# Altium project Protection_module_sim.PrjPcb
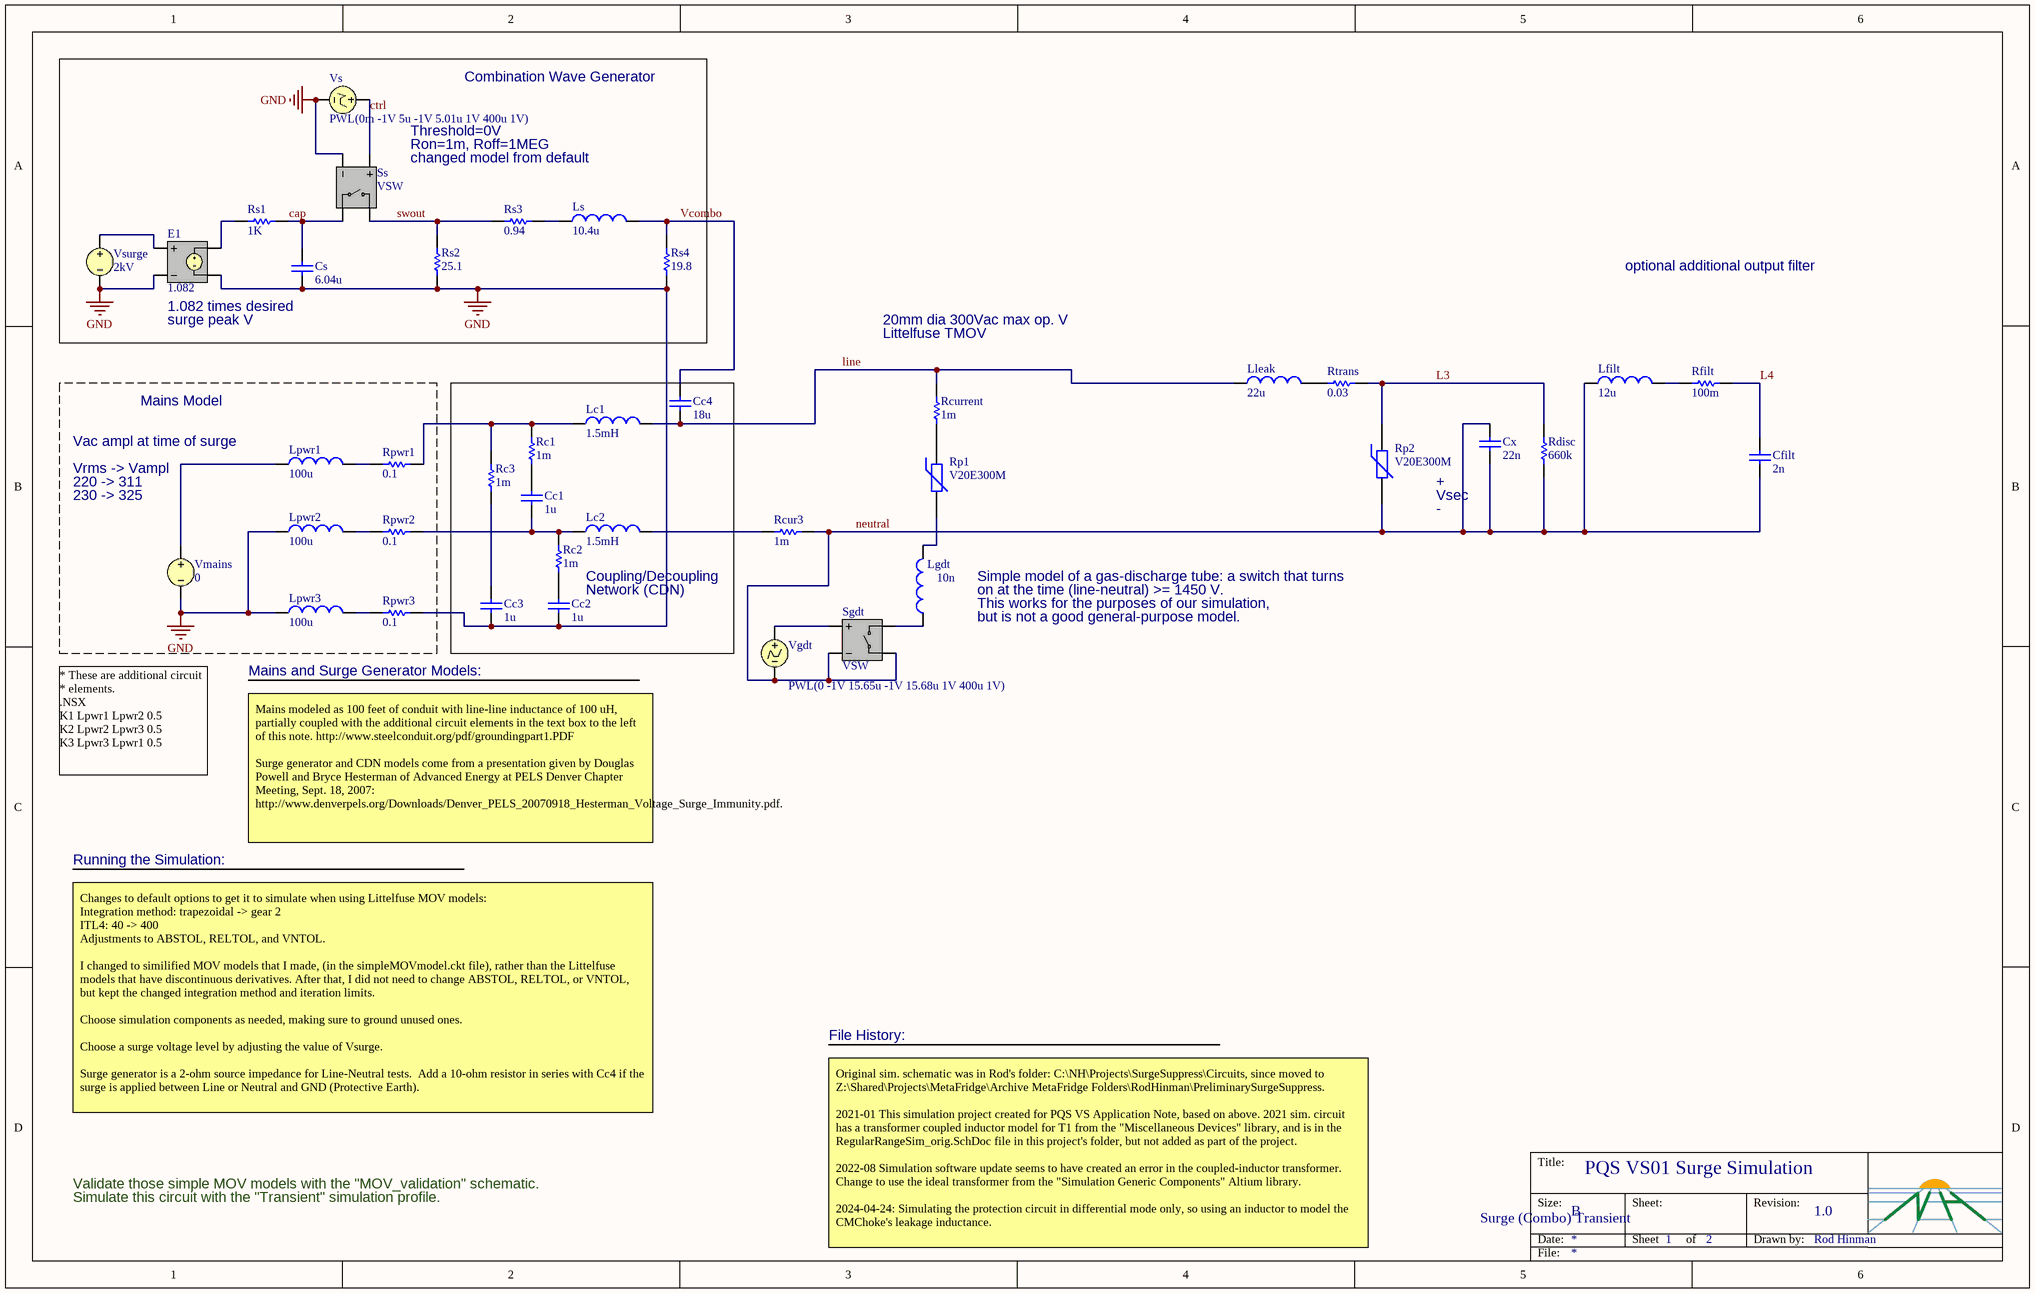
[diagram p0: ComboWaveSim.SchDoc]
nhEngName: Rod Hinman; nhProjName: PQS VS01 Surge Simulation; nhRev: 1.0; nhSheetTotal: 2
2 sheets, 52 parts. Net scope: global (net labels, ports and power ports of the same name join across sheets).
Sheets:
  ComboWaveSim.SchDoc
  MOV_validation.SchDoc

## Sheet ComboWaveSim.SchDoc: Simulation of Surge Test Combination Wave
size B; SheetNumber: 1; PageSetup: Record=PageOptions¦CenterHorizontal=True¦CenterVertical=True¦PrintScale=0.72¦XCorrection=1.00¦YCorrection=1.00¦PrintKind=0¦BorderSize=5000000¦LeftOffset=0¦BottomOffset=0¦Orientation=2¦PaperLength=1000¦PaperWidth=1000¦Scale=100¦PaperSource=7¦PrintQuality=-4¦MediaType=1¦DitherType=10¦PrintScaleMode=1¦PaperKind=Letter¦PaperIndex=1; nhSheetName: Surge (Combo) Transient; SPICEModelCacheWJGPQAWH: <root> / <DocumentId>WJGPQAWH</DocumentId> / <CacheFrame Number="0"> / <Model Name="vlowr" Kind="mdl"> / <Text>.MODEL VLOWR VSWITCH(RON=1m ROFF=1MEG)</Text> / </Model> / <Model Name="v20e300m" Kind="CKT"> / <Text>* Littelfuse UMOV V20E300: 20 mm disc 300VAC working voltage / * This curve was fit starting with two points from the max. clamping curve: / * Current Datasheet  Simulation with Io=0.6e-3 / *    10A  675V       612V / *   100A  775V       760V / *  1000A  920V       904V / * Then simulating and seeing the results. / * Using the first two points (which is where we'd like to operate in a dual-MOV system) / * Vo = 43.4V, Io = 4.8e-6A / * Using the second two points (100A, 1000A), we get: / * Vo = 63V, Io = 1.2e-3A / * These are on the _max_ curve, while it looks like Littelfuse simulates more typical values. / .subckt V20E300M 1 2 / R1 1 3 100u / B1 3 4 I=0.6e-3*(exp(abs(V(3,4))/63)-1)*sgn(V(3,4)) / C1 3 4 800pF / R2 3 4 4g / L1 4 2 12nH / .ends</Text> / </Model> / </CacheFrame> / </root>

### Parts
Cc1  1u  [RAD-0.3]
Cc2  1u  [RAD-0.3]
Cc3  1u  [RAD-0.3]
Cc4  18u  [RAD-0.3]
Cfilt  2n  [RAD-0.3]
Cs  6.04u  [RAD-0.3]
Cx  22n  [RAD-0.3]
E1  1.082
Lc1  1.5mH  [0402-A]
Lc2  1.5mH  [0402-A]
Lfilt  12u  [0402-A]
Lgdt  10n  [0402-A]
Lleak  22u  [0402-A]
Lpwr1  100u  [0402-A]
Lpwr2  100u  [0402-A]
Lpwr3  100u  [0402-A]
Ls  10.4u  [0402-A]
Rc1  1m  [AXIAL-0.3]
Rc2  1m  [AXIAL-0.3]
Rc3  1m  [AXIAL-0.3]
Rcur3  1m  [AXIAL-0.3]
Rcurrent  1m  [AXIAL-0.3]
Rdisc  660k  [AXIAL-0.3]
Rfilt  100m  [AXIAL-0.3]
Rp1  V20E300M  [6-0805_L]
Rp2  V20E300M  [6-0805_L]
Rpwr1  0.1  [AXIAL-0.3]
Rpwr2  0.1  [AXIAL-0.3]
Rpwr3  0.1  [AXIAL-0.3]
Rs1  1K  [AXIAL-0.3]
Rs2  25.1  [AXIAL-0.3]
Rs3  0.94  [AXIAL-0.3]
Rs4  19.8  [AXIAL-0.3]
Rtrans  0.03  [AXIAL-0.3]
Sgdt  VSW
Ss  VSW
Vgdt  PWL(0 -1V 15.65u -1V 15.68u 1V 400u 1V)
Vmains  0
Vs  PWL(0m -1V 5u -1V 5.01u 1V 400u 1V)
Vsurge  2kV

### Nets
GND: Cc2.2 Cc3.2 Cs.2 E1.2(NC-) E1.4(N-) Lpwr2.1 Lpwr3.1 Rpwr3.2 Rs2.1 Rs4.1 Ss.2(N1-) Vmains.2 Vs.2 Vsurge.2
cap: Cs.1 Rs1.2 Ss.4(N2-)
ctrl: Ss.1(N1+) Vs.1
L3: Rdisc.2 Rp2.1 Rtrans.2
L4: Cfilt.1 Rfilt.1
line: Cc4.2 Lc1.2 Lleak.1 Rcurrent.1
neutral: Cfilt.2 Cx.1 Cx.2 Lfilt.1 Rcur3.1 Rdisc.1 Rp2.2 Sgdt.2(N1-) Sgdt.4(N2-) Vgdt.2
swout: Rs2.2 Rs3.2 Ss.3(N2+)
Vcombo: Cc4.1 Ls.2 Rs4.2
NetCc1_1: Cc1.1 Rc1.2
NetCc1_2: Cc1.2 Lc2.1 Rc2.1 Rpwr2.2
NetCc2_1: Cc2.1 Rc2.2
NetCc3_1: Cc3.1 Rc3.2
NetE1_1: E1.1(NC+) Vsurge.1
NetE1_3: E1.3(N+) Rs1.1
NetLc1_1: Lc1.1 Rc1.1 Rc3.1 Rpwr1.2
NetLc2_2: Lc2.2 Rcur3.2
NetLfilt_2: Lfilt.2 Rfilt.2
NetLgdt_1: Lgdt.1 Sgdt.3(N2+)
NetLgdt_2: Lgdt.2 Rp1.2
NetLleak_2: Lleak.2 Rtrans.1
NetLpwr1_1: Lpwr1.1 Vmains.1
NetLpwr1_2: Lpwr1.2 Rpwr1.1
NetLpwr2_2: Lpwr2.2 Rpwr2.1
NetLpwr3_2: Lpwr3.2 Rpwr3.1
NetLs_1: Ls.1 Rs3.1
NetRcurrent_2: Rcurrent.2 Rp1.1
NetSgdt_1: Sgdt.1(N1+) Vgdt.1

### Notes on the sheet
- Combination Wave Generator
- changed model from default
- Ron=1m, Roff=1MEG
- Threshold=0V
- optional additional output filter
- 1.082 times desired
- surge peak V
- 20mm dia 300Vac max op. V
- Littelfuse TMOV
- Mains Model
- Vrms -> Vampl
- 220 -> 311
- (near Lpwr1) Vac ampl at time of surge
- 230 -> 325
- Vsec
- +
- -
- Coupling/Decoupling
- Network (CDN)
- Simple model of a gas-discharge tube: a switch that turns
- on at the time (line-neutral) >= 1450 V.
- This works for the purposes of our simulation,
- but is not a good general-purpose model.
- Mains and Surge Generator Models:
- * These are additional circuit
  * elements.
  .NSX
  K1 Lpwr1 Lpwr2 0.5
  K2 Lpwr2 Lpwr3 0.5
  K3 Lpwr3 Lpwr1 0.5
- Mains modeled as 100 feet of conduit with line-line inductance of 100 uH, partially coupled with the additional circuit elements in the text box to the left of this note. http://www.steelconduit.org/pdf/groundingpart1.PDF
  Surge generator and CDN models come from a presentation given by Douglas Powell and Bryce Hesterman of Advanced Energy at PELS Denver Chapter Meeting, Sept. 18, 2007: http://www.denverpels.org/Downloads/Denver_PELS_20070918_Hesterman_Voltage_Surge_Immunity.pdf.
- Running the Simulation:
- File History:
- Changes to default options to get it to simulate when using Littelfuse MOV models:
  Integration method: trapezoidal -> gear 2
  ITL4: 40 -> 400
  Adjustments to ABSTOL, RELTOL, and VNTOL.
  I changed to similified MOV models that I made, (in the simpleMOVmodel.ckt file), rather than the Littelfuse models that have discontinuous derivatives. After that, I did not need to change ABSTOL, RELTOL, or VNTOL, but kept the changed integration method and iteration limits.
  Choose simulation components as needed, making sure to ground unused ones.
  Choose a surge voltage level by adjusting the value of Vsurge.
  Surge generator is a 2-ohm source impedance for Line-Neutral tests.  Add a 10-ohm resistor in series with Cc4 if the surge is applied between Line or Neutral and GND (Protective Earth).
- Validate those simple MOV models with the "MOV_validation" schematic.
- Simulate this circuit with the "Transient" simulation profile.
- Original sim. schematic was in Rod's folder: C:\NH\Projects\SurgeSuppress\Circuits, since moved to Z:\Shared\Projects\MetaFridge\Archive MetaFridge Folders\RodHinman\PreliminarySurgeSuppress.
  2021-01 This simulation project created for PQS VS Application Note, based on above. 2021 sim. circuit has a transformer coupled inductor model for T1 from the "Miscellaneous Devices" library, and is in the RegularRangeSim_orig.SchDoc file in this project's folder, but not added as part of the project.
  2022-08 Simulation software update seems to have created an error in the coupled-inductor transformer. Change to use the ideal transformer from the "Simulation Generic Components" Altium library.
  2024-04-24: Simulating the protection circuit in differential mode only, so using an inductor to model the CMChoke's leakage inductance.

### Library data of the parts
Cc1-Cc4 Cfilt Cs Cx = Cap: Capacitor
E1 = ESRC: Voltage Controlled Voltage Source; Note: PCB Footprint - Not required; Sim Note: Enter gain into gain field
Lc1 Lc2 Lfilt Lgdt Lleak Lpwr1-Lpwr3 Ls = Inductor: Code_IEC: 1005
Rc1-Rc3 Rcur3 Rcurrent Rdisc Rfilt Rpwr1-Rpwr3 Rs1-Rs4 Rtrans = Res1: Resistor
Rp1 Rp2 = Res Varistor: Varistor (Voltage-Sensitive Resistor)
Sgdt Ss = VSW: Voltage Controlled Switch
Vgdt = VPWL: Piecewise Linear Voltage Source; Note: PCB Footprint - Not required; Sim Note: To add model file containing time-current pairs of values, enter model location under "General Tab" in "Full Path" box.; Time-Value Pairs: 0 -1V 5.65u -1V 5.68u 1V 400u 1V; DC Magnitude: -1; AC Magnitude: 0
Vmains Vsurge = VSRC: Voltage Source; Note: PCB Footprint - Not required
Vs = VPWL: Piecewise Linear Voltage Source; Note: PCB Footprint - Not required; Sim Note: To add model file containing time-current pairs of values, enter model location under "General Tab" in "Full Path" box.; DC Magnitude: -1; AC Magnitude: 0

## Sheet MOV_validation.SchDoc: Simulation of Surge Test Combination Wave
size B; SheetNumber: 2; PageSetup: Record=PageOptions¦CenterHorizontal=True¦CenterVertical=True¦PrintScale=0.72¦XCorrection=1.00¦YCorrection=1.00¦PrintKind=0¦BorderSize=5000000¦LeftOffset=0¦BottomOffset=0¦Orientation=2¦PaperLength=1000¦PaperWidth=1000¦Scale=100¦PaperSource=7¦PrintQuality=-4¦MediaType=1¦DitherType=10¦PrintScaleMode=1¦PaperKind=Letter¦PaperIndex=1; nhSheetName: MOV Validation; SPICEModelCacheEVEGFIEB: <root> / <DocumentId>EVEGFIEB</DocumentId> / <CacheFrame Number="0"> / <Model Name="v20e510m" Kind="ckt"> / <Text>.subckt V20E510M 1 2 / R1 1 3 100u / B1 3 4 I=3.2e-4*(exp(abs(V(3,4))/87)-1)*sgn(V(3,4)) / C1 3 4 350pF / R2 3 4 4g / L1 4 2 12nH / .ends</Text> / </Model> / <Model Name="umov" Kind="CKT"> / <Text>.SUBCKT UMOV  1 2 PARAMS: T=1 C=1pF L=1nH a1=1 a2=0 a3=0 a4=0 a5=0 a6=100u a7=100u / E_non_lin	3 1	VALUE {T*( / +	10^( / +	+a1+a2*(log10(limit(v(4),a7,1g))-3) / +	+a3*2^(-log10(limit(v(4),a7,1g))+3) / +	+a4*exp(-log10(limit(v(4),a7,1g))+3) / +	+a5*exp(log10(limit(v(4),a7,1g))-3) / +	+a6*2^(log10(limit(v(4),a7,1g))-3) / +	) / +	-10^( / +	a1+a2*(log10(-limit(v(4),-1g,-a7))-3) / +	+a3*2^(-log10(-limit(v(4),-1g,-a7))+3) / +	+a4*exp(-log10(-limit(v(4),-1g,-a7))+3) / +	+a5*exp(log10(-limit(v(4),-1g,-a7))-3) / +	+a6*2^(log10(-limit(v(4),-1g,-a7))-3) / +	) / +	+limit(v(4)/a7*v(8),-v(8),v(8)) / +	)} / L_series	5 6  {L} / H_H1		4 0  VH_H1 1k / VH_H1		5 70 0V / R_R2		0 4  1G / R_series	6 2  100u / V_V1		3 70  0V / E_x_zero	8 0 	VALUE {10^( / +	a1+a2*(log10(a7/1e3)) / +	+a3*2^(-log10(a7/1e3)) / +	+a4*exp(-log10(a7/1e3)) / +	+a5*exp(log10(a7/1e3)) / +	+a6*2^(log10(a7/1e3)) / +	)} / R_x_zero	8 0  1G / C_parallel	1 5 {C} / .ENDS</Text> / </Model> / <Model Name="v20e510" Kind="ckt"> / <Text>.SUBCKT V20E510 1 2 PARAMS: TOL=0 / X1	1 2	UMOV PARAMS: T={1+TOL/100} L=12nH C=350pF a1=3.006 a2=5.574E-2 a3=1.837E-2 a4=-3.412E-3 a5=1.362E-2 a6=-3.772E-2 / .ENDS</Text> / <Dependency>0\umov</Dependency> / </Model> / <Model Name="v20e140" Kind="ckt"> / <Text>.SUBCKT V20E140 1 2 PARAMS: TOL=0 / X1	1 2	UMOV PARAMS: T={1+TOL/100} L=12nH C=1.75nF a1=2.429 a2=4.817E-2 a3=1.273E-2 a4=-2.058E-3 a5=1.193E-2 a6=-2.71E-2 / .ENDS</Text> / <Dependency>0\umov</Dependency> / </Model> / <Model Name="v20e140t" Kind="ckt"> / <Text>.subckt V20E140T 1 2 / R1 1 3 100u / B1 3 4 I=7.4e-3*(exp(abs(V(3,4))/33.8)-1)*sgn(V(3,4)) / C1 3 4 1.75nF / R2 3 4 4g / L1 4 2 12nH / .ends</Text> / </Model> / <Model Name="v20e420" Kind="ckt"> / <Text>.SUBCKT V20E420 1 2 PARAMS: TOL=0 / X1	1 2	UMOV PARAMS: T={1+TOL/100} L=12nH C=600pF a1=2.925 a2=5.574E-2 a3=1.837E-2 a4=-3.412E-3 a5=1.362E-2 a6=-3.772E-2 / .ENDS</Text> / <Dependency>0\umov</Dependency> / </Model> / <Model Name="v20e420m" Kind="ckt"> / <Text>.subckt V20E420M 1 2 / R1 1 3 100u / B1 3 4 I=3.2e-4*(exp(abs(V(3,4))/87)-1)*sgn(V(3,4)) / C1 3 4 600pF / R2 3 4 4g / L1 4 2 12nH / .ends</Text> / </Model> / <Model Name="v20e275" Kind="ckt"> / <Text>.SUBCKT V20E275 1 2 PARAMS: TOL=0 / X1	1 2	UMOV PARAMS: T={1+TOL/100} L=12nH C=900pF a1=2.726 a2=5.574E-2 a3=1.837E-2 a4=-3.412E-3 a5=1.362E-2 a6=-3.772E-2 / .ENDS</Text> / <Dependency>0\umov</Dependency> / </Model> / <Model Name="v20e275m" Kind="ckt"> / <Text>.subckt V20E275M 1 2 / R1 1 3 100u / B1 3 4 I=1.5e-12*(exp(abs(V(3,4))/22)-1)*sgn(V(3,4)) / C1 3 4 900pF / R2 3 4 4g / L1 4 2 12nH / .ends</Text> / </Model> / <Model Name="v20e385t" Kind="CKT"> / <Text>* Littelfuse UMOV V20E385: 20 mm disc 385VAC working voltage / * This curve was fit starting with two points from the Littelfuse model's simulation: / * Current Sim Their  Simulation Our Model / *    10A  xxxV       V - 418V - the curve is too soft in the lower current regions and doesn't model so well here. / *   100A  xxxV       V - 518V - model is good above about 80A / *  1000A  xxxV       V - 617V / * Then simulating and seeing the results. / * Using the second two points (which is where we'd like to operate in a dual-MOV system with 230V+GDT in front) / * Vo = 43.0V, Io = 5.9e-4A / .subckt V20E385T 1 2 / R1 1 3 100u / B1 3 4 I=5.9e-4*(exp(abs(V(3,4))/43)-1)*sgn(V(3,4)) / C1 3 4 700pF / R2 3 4 4g / L1 4 2 12nH / .ends</Text> / </Model> / <Model Name="v20e385" Kind="CKT"> / <Text>* / .SUBCKT V20E385 1 2 PARAMS: TOL=0 / X1	1 2	UMOV PARAMS: T={1+TOL/100} L=12nH C=700pF a1=2.885 a2=5.574E-2 a3=1.837E-2 a4=-3.412E-3 a5=1.362E-2 a6=-3.772E-2 / .ENDS</Text> / <Dependency>1\umov</Dependency> / </Model> / </CacheFrame> / <CacheFrame Number="1"> / <Model Name="umov" Kind="CKT"> / <Text>******************************* / *Varistor PSpice Model Netlist* / ******************************* / * / * ? 	Littelfuse Inc. / * / *     March 25, 2003 / *	version 4.2 / * / * Representing typical characteristics for the following UltraMOV series varistors: / * / *V20E130 V20E140 V20E150 V20E175 V20E200 / *V20E230 V20E250 V20E275 V20E300 / *V20E320 V20E385 V20E420 V20E440 / *V20E460 V20E510 V20E550 V20E625 / * / .SUBCKT UMOV  1 2 PARAMS: T=1 C=1pF L=1nH a1=1 a2=0 a3=0 a4=0 a5=0 a6=100u a7=100u / E_non_lin	3 1	VALUE {T*( / +	10^( / +	+a1+a2*(log10(limit(v(4),a7,1g))-3) / +	+a3*2^(-log10(limit(v(4),a7,1g))+3) / +	+a4*exp(-log10(limit(v(4),a7,1g))+3) / +	+a5*exp(log10(limit(v(4),a7,1g))-3) / +	+a6*2^(log10(limit(v(4),a7,1g))-3) / +	) / +	-10^( / +	a1+a2*(log10(-limit(v(4),-1g,-a7))-3) / +	+a3*2^(-log10(-limit(v(4),-1g,-a7))+3) / +	+a4*exp(-log10(-limit(v(4),-1g,-a7))+3) / +	+a5*exp(log10(-limit(v(4),-1g,-a7))-3) / +	+a6*2^(log10(-limit(v(4),-1g,-a7))-3) / +	) / +	+limit(v(4)/a7*v(8),-v(8),v(8)) / +	)} / L_series	5 6  {L} / H_H1		4 0  VH_H1 1k / VH_H1		5 70 0V / R_R2		0 4  1G / R_series	6 2  100u / V_V1		3 70  0V / E_x_zero	8 0 	VALUE {10^( / +	a1+a2*(log10(a7/1e3)) / +	+a3*2^(-log10(a7/1e3)) / +	+a4*exp(-log10(a7/1e3)) / +	+a5*exp(log10(a7/1e3)) / +	+a6*2^(log10(a7/1e3)) / +	)} / R_x_zero	8 0  1G / C_parallel	1 5 {C} / .ENDS</Text> / </Model> / </CacheFrame> / </root>
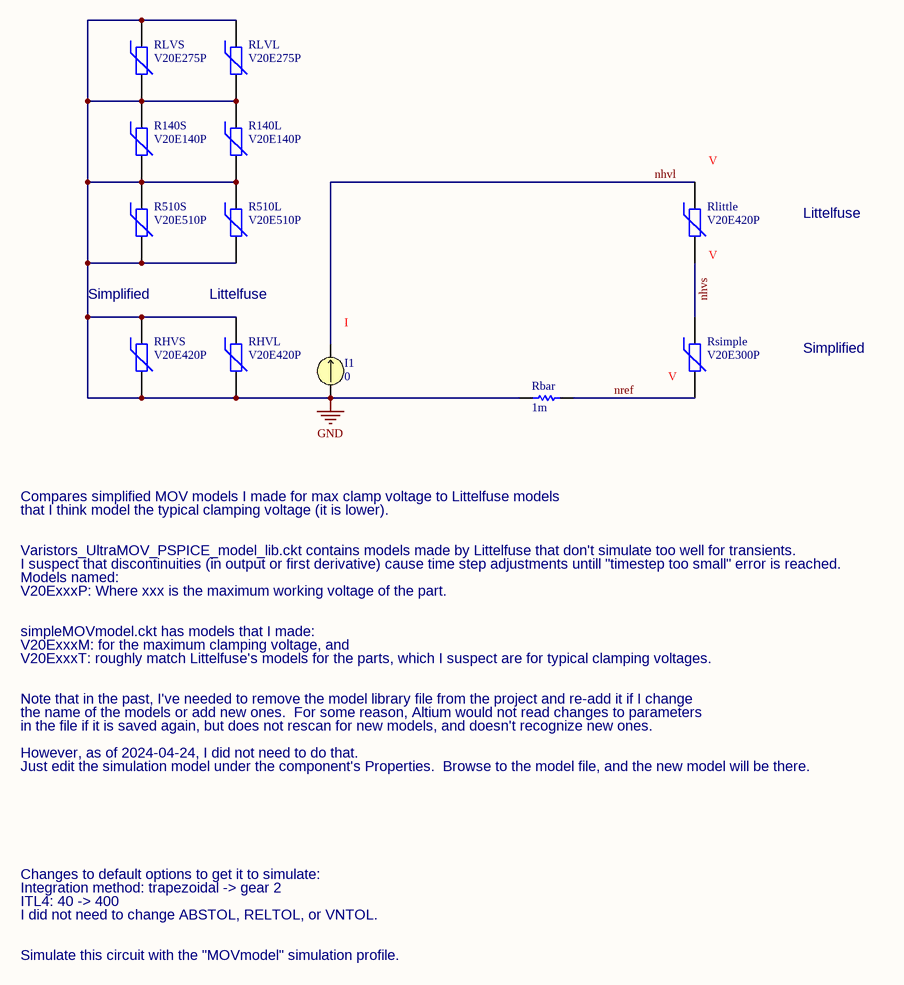
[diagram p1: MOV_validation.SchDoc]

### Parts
I1  value 0  (hidden comment: ISRC)
R140L  V20E140P  [6-0805_L]
R140S  V20E140P  [6-0805_L]
R510L  V20E510P  [6-0805_L]
R510S  V20E510P  [6-0805_L]
Rbar  1m  [AXIAL-0.3]
RHVL  V20E420P  [6-0805_L]
RHVS  V20E420P  [6-0805_L]
Rlittle  V20E420P  [6-0805_L]
RLVL  V20E275P  [6-0805_L]
RLVS  V20E275P  [6-0805_L]
Rsimple  V20E300P  [6-0805_L]

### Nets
GND: I1.1 R140L.1 R140L.2 R140S.1 R140S.2 R510L.1 R510L.2 R510S.1 R510S.2 Rbar.2 RHVL.1 RHVL.2 RHVS.1 RHVS.2 RLVL.1 RLVL.2 RLVS.1 RLVS.2
nhvl: I1.2 Rlittle.1
nhvs: Rlittle.2 Rsimple.1
nref: Rbar.1 Rsimple.2

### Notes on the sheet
- Littelfuse
- Simplified
- Compares simplified MOV models I made for max clamp voltage to Littelfuse models
- that I think model the typical clamping voltage (it is lower).
- Varistors_UltraMOV_PSPICE_model_lib.ckt contains models made by Littelfuse that don't simulate too well for transients.
- I suspect that discontinuities (in output or first derivative) cause time step adjustments untill "timestep too small" error is reached.
- Models named:
- V20ExxxP: Where xxx is the maximum working voltage of the part.
- simpleMOVmodel.ckt has models that I made:
- V20ExxxM: for the maximum clamping voltage, and
- V20ExxxT: roughly match Littelfuse's models for the parts, which I suspect are for typical clamping voltages.
- Note that in the past, I've needed to remove the model library file from the project and re-add it if I change
- the name of the models or add new ones.  For some reason, Altium would not read changes to parameters
- in the file if it is saved again, but does not rescan for new models, and doesn't recognize new ones.
- However, as of 2024-04-24, I did not need to do that.
- Just edit the simulation model under the component's Properties.  Browse to the model file, and the new model will be there.
- Changes to default options to get it to simulate:
- Integration method: trapezoidal -> gear 2
- ITL4: 40 -> 400
- I did not need to change ABSTOL, RELTOL, or VNTOL.
- Simulate this circuit with the "MOVmodel" simulation profile.

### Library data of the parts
I1 = ISRC: Current Source; Note: PCB Footprint - Not required
R140L R140S R510L R510S RHVL RHVS Rlittle RLVL RLVS Rsimple = Res Varistor: Varistor (Voltage-Sensitive Resistor)
Rbar = Res1: Resistor

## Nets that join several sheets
GND: ComboWaveSim (14 pins), MOV_validation (18 pins)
